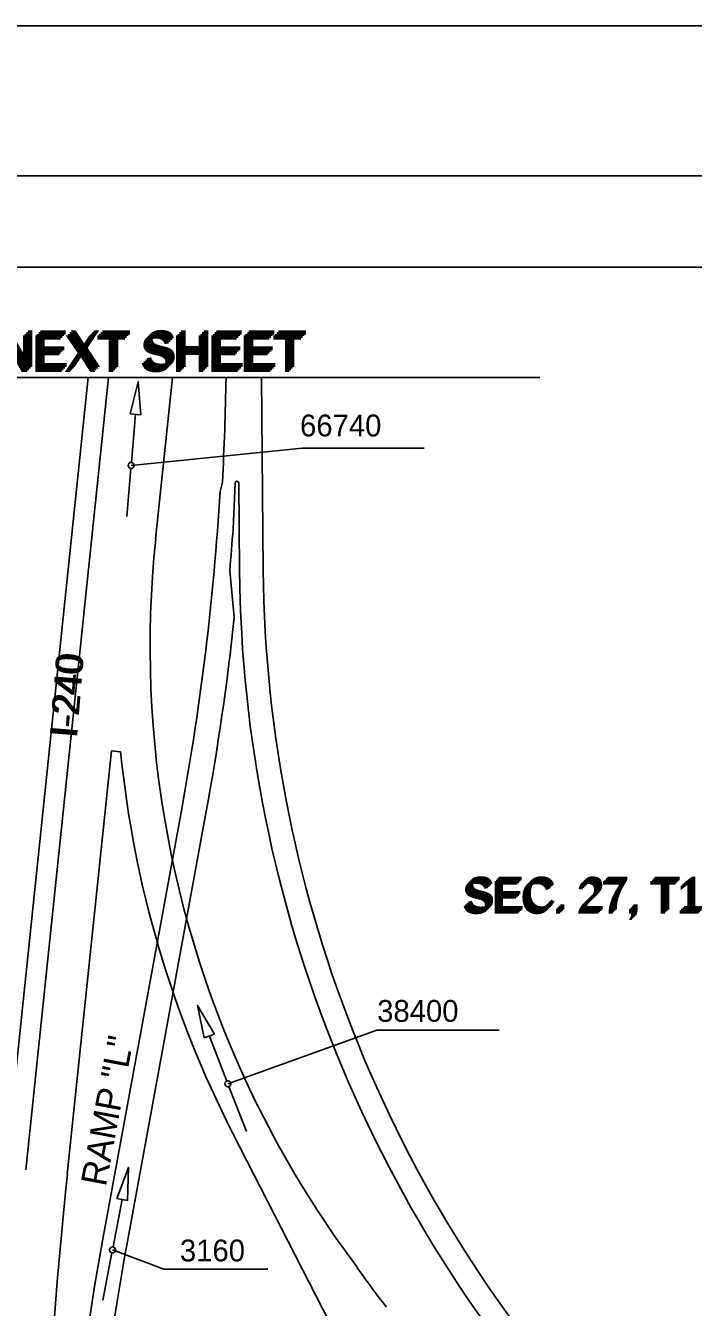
# Model space of a CAD drawing. Extents: x 137200 to 144400, y -2153713 to -2148447.
# Drawn here: x 142762 to 143494, y -2149854 to -2148447 of the extents above; entities that cross this region are included whole.
import ezdxf

# ---------------------------------------------------------------- set-up
doc = ezdxf.new("R2010")
doc.units = 0
for name, color, linetype in [('4', 7, 'Continuous'), ('5', 7, 'Continuous'), ('6', 7, 'Continuous'), ('PROP', 7, 'Continuous'), ('SHT_Plot_Shape_Full', 7, 'Continuous'), ('SHT_Plot_Shape_Half', 7, 'Continuous'), ('SHT_Sheet_Border', 7, 'Continuous'), ('T', 7, 'Continuous')]:
    doc.layers.add(name, color=color, linetype=linetype)

# ---------------------------------------------------------------- blocks, each defined once
blk = doc.blocks.new('ARR')
at = {"layer": '6'}
for p, q in [((134.5, 0), (0, 0)), ((285.8, 0), (151.3, 0))]:
    blk.add_line(p, q, dxfattribs=at)
blk.add_lwpolyline([(285.8, 15.2), (285.8, -15.2), (377.2, 0)], close=True, dxfattribs=at)
blk.add_circle((142.9, 0), 8.42, dxfattribs=at)

msp = doc.modelspace()

# ---------------------------------------------------------------- linework, layer by layer
at = {"layer": '4'}
for p, q in [((142844.2, -2148833.3), (142201, -2148833.3)), ((142762.8, -2148833.3), (143325.9, -2148833.3))]:
    msp.add_line(p, q, dxfattribs=at)
at = {"layer": '6'}
for p, q in [((143065.2, -2148910.9), (142877.8, -2148929.8)), ((143199.2, -2148910.9), (143065.2, -2148910.9)), ((142983.9, -2149608.8), (143147.4, -2149549.8)), ((143147.4, -2149549.8), (143281.4, -2149549.8)), ((142913.4, -2149812.2), (142857.2, -2149791)), ((143027.6, -2149812.2), (142913.4, -2149812.2))]:
    msp.add_line(p, q, dxfattribs=at)
at = {"layer": 'PROP'}
for p, q in [((142830.6, -2148833.3), (142740.1, -2149700.9)), ((142852.7, -2148833.3), (142762, -2149703.2)), ((142904.6, -2149010.7), (142923.1, -2148833.3)), ((143020.7, -2148833.3), (143022.7, -2149044.9)), ((142975.2, -2148958.3), (142977.8, -2148948.4)), ((142989.5, -2148999.4), (142991.8, -2148949.2)), ((142995.7, -2148949.3), (142996.7, -2149045.1)), ((142990.9, -2149096.4), (142985.8, -2149045.6)), ((142856.2, -2149243), (142807.7, -2149707.9)), ((142866.2, -2149244.1), (142856.2, -2149243)), ((142846.3, -2149781), (142933.2, -2149306.8)), ((142872.8, -2149785.9), (142959.8, -2149311.7)), ((143299.7, -2150269.9), (142989.3, -2149663.2))]:
    msp.add_line(p, q, dxfattribs=at)
for centre, radius, start, end in [((140117.3, -2148790.7), 2864.8, 356.8446, 359.1474), ((142993.7, -2148949.3), 2, 0.5432, 176.8446), ((142993.7, -2148949.3), 2, 0.5432, 176.8446), ((140117.3, -2148790.7), 2862.8, 349.6136, 356.6446), ((140117.3, -2148790.7), 2879.8, 354.9229, 355.8446), ((144034.4, -2149128.5), 1135.9, 174.0443, 207.0949), ((144442, -2149031.4), 1445.4, 180.5432, 223.7809), ((144442, -2149031.4), 1419.4, 180.5432, 223.7809), ((140117.3, -2148790.7), 2889.8, 349.6136, 353.9281), ((144034.4, -2149128.5), 1173.9, 185.6499, 207.0949), ((144034.4, -2149128.5), 1135.9, 207.0949, 216.6184), ((144034.4, -2149128.5), 1135.9, 207.0949, 216.6184), ((148449.7, -2150296.5), 5672.6, 174.0443, 180.4098), ((145680.9, -2150300.6), 2881.8, 169.6136, 180.4098), ((145680.9, -2150300.6), 2854.8, 169.6136, 173.2156), ((144057.4, -2149158.9), 1136.9, 214.6938, 217.6955)]:
    msp.add_arc(centre, radius, start, end, dxfattribs=at)
at = {"layer": 'SHT_Plot_Shape_Full'}
msp.add_lwpolyline([(137199.8, -2148447.1), (144399.8, -2148447.1), (144399.8, -2153247.1), (137199.8, -2153247.1)], close=True, dxfattribs=at)
at = {"layer": 'SHT_Plot_Shape_Half'}
msp.add_lwpolyline([(137527.3, -2148612.1), (144327.3, -2148612.1), (144327.3, -2153012.1), (137527.3, -2153012.1)], close=True, dxfattribs=at)
at = {"layer": 'SHT_Sheet_Border'}
msp.add_lwpolyline([(144217.3, -2152912.1), (137917.3, -2152912.1), (137917.3, -2148712.1), (144217.3, -2148712.1)], close=True, dxfattribs=at)

# ---------------------------------------------------------------- block references
at = {"layer": '6'}
for p, xscale, yscale, rotation in [((142873, -2148985.9), 0.39370000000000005, 0.3937, 85.15706944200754), ((143004.1, -2149661.2), 0.39370000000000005, 0.3937000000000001, 111.11949947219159), ((142846.6, -2149846.3), 0.3937, 0.39370000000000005, 79.11008947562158)]:
    msp.add_blockref('ARR', p, dxfattribs=dict(at, xscale=xscale, yscale=yscale, rotation=rotation))

# ---------------------------------------------------------------- texts
at = {"layer": '4'}
msp.add_text('RAMP "L"', height=28, rotation=79.3747, dxfattribs=at).set_placement((142849.9, -2149722.3))
at = {"layer": '5'}
for p in [(142818.4, -2149227.9), (142818.2, -2149229.9)]:
    msp.add_text('I-240', height=30, rotation=85.3032, dxfattribs=at).set_placement(p)
for p in [(143240.3, -2149422.1), (143241.9, -2149420.5), (143243.5, -2149418.9), (143245, -2149417.4)]:
    msp.add_text('SEC. 27, T11N, R3W', height=36, dxfattribs=at).set_placement(p)
at = {"layer": 'T'}
for s, height, p in [('MATCH LINE 2 SEE NEXT SHEET', 40, (142225.9, -2148825.4)), ('MATCH LINE 2 SEE NEXT SHEET', 40, (142227.8, -2148823.5)), ('MATCH LINE 2 SEE NEXT SHEET', 40, (142229.6, -2148821.7)), ('MATCH LINE 2 SEE NEXT SHEET', 40, (142224.1, -2148827.2)), ('66740', 24, (143063, -2148898)), ('38400', 24, (143147.6, -2149540.7)), ('3160', 24, (142931.2, -2149803.7))]:
    msp.add_text(s, height=height, dxfattribs=at).set_placement(p)

doc.saveas('drawing.dxf')
